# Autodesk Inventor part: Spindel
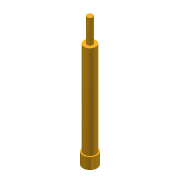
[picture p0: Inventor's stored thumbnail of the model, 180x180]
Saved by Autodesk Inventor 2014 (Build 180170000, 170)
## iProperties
Created: 2014-03
Part Number: Spindel
Material: Generisch
Document SubType Name: Modeling
Designer: e_dammj
Density: 1 g/cm^3
Appearance: Vorgabe
Sending System: SolidWorks 2011
Last Author: e_boekem
Author: e_dammj
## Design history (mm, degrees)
node "Spindel.ipt1"
node "Aufsatz-Linear austragen2"
node "Basis1"
